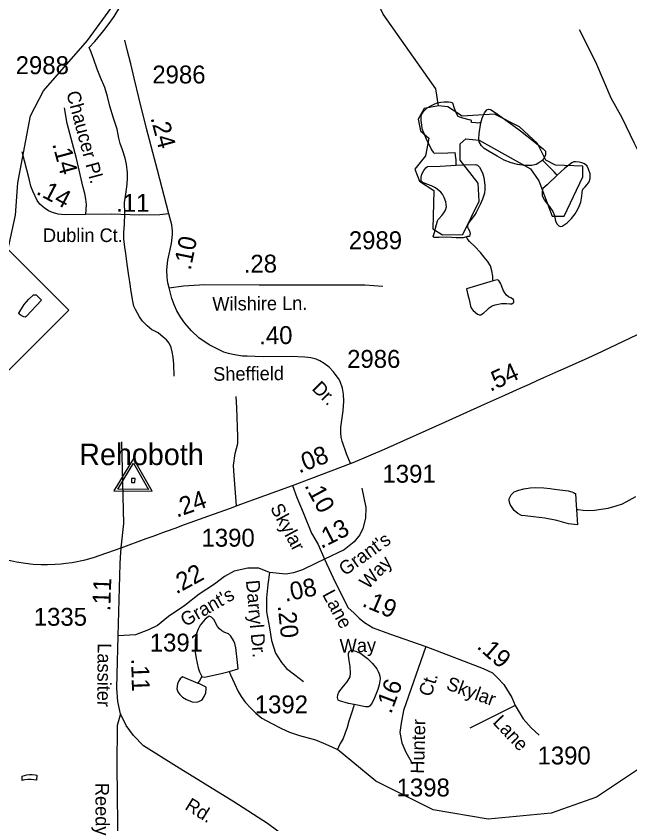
# Model space of a CAD drawing. Extents: x 2082433 to 2279600, y 546599 to 755198.
# Drawn here: x 2142696 to 2146984, y 638629 to 644267 of the extents above; entities that cross this region are included whole.
import ezdxf

# ---------------------------------------------------------------- set-up
doc = ezdxf.new("R2010")
doc.units = 0
for name, color, linetype in [('Exist Hydrographic Creek Single Shore', 7, 'Continuous'), ('Exist Hydrographic Misc Water Feature', 7, 'Continuous'), ('Exist Hydrographic Pond Under 1500 Sq Ft', 7, 'Continuous'), ('Exist Road Non-System Type 51', 7, 'Continuous'), ('Exist Road Primary NC Attributed', 7, 'Continuous'), ('Exist Road Primary NC Service Mileage Hundredths English Label', 7, 'Continuous'), ('Exist Road Primary NC Shield CELL', 7, 'Continuous'), ('Exist Road Secondary Mileage Hundredths English Label', 7, 'Continuous'), ('Exist Road Secondary Type 51 Attributed', 7, 'Continuous'), ('Exist Road Secondary Type 51 Label', 7, 'Continuous'), ('Exist Road Secondary Type 51 Number Label', 7, 'Continuous'), ('Exist Survey Geodetic Marker CELL', 7, 'Continuous'), ('Exist Survey Geodetic Marker Label', 7, 'Continuous')]:
    doc.layers.add(name, color=color, linetype=linetype)

msp = doc.modelspace()

# ---------------------------------------------------------------- linework, layer by layer
at = {"layer": 'Exist Hydrographic Creek Single Shore'}
for points in [[(2144184.1, 639693.2), (2144194.2, 639669.4), (2144220.4, 639607.4), (2144246.7, 639553.6), (2144268.8, 639517.8), (2144297.1, 639477.8), (2144335, 639436), (2144371.3, 639400.5), (2144413.2, 639366.5), (2144477.3, 639330.9), (2144549.7, 639295.2), (2144605.7, 639269.3), (2144675.8, 639245.7), (2144736.1, 639230.1), (2144787.8, 639214.2), (2144844.2, 639192.7), (2144902.4, 639166.8), (2144940.3, 639146.9)], [(2148888.3, 639225.1), (2148289, 639204.5), (2147722.8, 639068.4), (2147448.9, 639051), (2147373.8, 639065.6), (2147098.8, 639048.2), (2146749.8, 638815.8), (2146433.8, 638704.2), (2145992.8, 638660.7), (2145608.9, 638727.5), (2145207.8, 638925.9), (2144940.3, 639146.9)]]:
    msp.add_lwpolyline(points, dxfattribs=at)
at = {"layer": 'Exist Hydrographic Misc Water Feature'}
for points in [[(2142425.9, 640770.2), (2142423.9, 641127.8), (2142389.8, 641502.4), (2142471.8, 641668.1), (2142495.8, 641926.7), (2142528.9, 642021.2), (2142625.9, 642576.9), (2142691.9, 642877.3), (2142706.9, 643103.4), (2142796.9, 643570.6), (2142887.9, 643745.9), (2143194.9, 644097.2), (2143509.1, 644530.4), (2143681.9, 644891), (2143781, 645174.4), (2143996.1, 645534.1), (2144103.9, 645600.8), (2144321.1, 645602.9), (2144613.1, 645452.7), (2144805, 645419.3)], [(2145645.9, 643640.7), (2145628.1, 643759.1), (2145260, 644281.6), (2145134.1, 644546.6), (2144882.1, 644853.5), (2144907.1, 645046.5)], [(2143205.2, 644047.4), (2143245, 644089.7), (2143308.7, 644166), (2143346.5, 644214.2), (2143380.3, 644264.3), (2143419.9, 644330.5), (2143435.7, 644354.4), (2143461.9, 644386.6), (2143491.7, 644422.6), (2143529.4, 644464.8), (2143571.2, 644509.2), (2143585.2, 644527.3), (2143600.7, 644557), (2143620.6, 644599.4), (2143626.8, 644621.2), (2143642, 644697.2)], [(2143800.9, 641753), (2143797, 641836.8), (2143792.7, 641886.9), (2143786.7, 641922.7), (2143778.5, 641952.7), (2143764, 641982.9), (2143746.3, 642006.7), (2143724.2, 642026.6), (2143687.9, 642056.5), (2143660, 642070.4), (2143643.8, 642078.2), (2143611.6, 642106.1), (2143577.8, 642138), (2143557.7, 642167.8), (2143529.4, 642219.6), (2143519.3, 642243.4), (2143510.9, 642277.5), (2143500.7, 642343.5), (2143490.2, 642411.6), (2143484.1, 642453.5), (2143471.8, 642535.3), (2143463.4, 642609.2), (2143455.2, 642655), (2143449.2, 642713.1), (2143448.8, 642757), (2143452.5, 642815.2), (2143456.4, 642889.2), (2143453.7, 642965.1), (2143461.5, 643025.1), (2143471.1, 643093), (2143473, 643137), (2143473, 643173), (2143466.4, 643232.9), (2143458.6, 643275), (2143438.5, 643332.8), (2143421.9, 643376.6), (2143413.9, 643414.8), (2143401.6, 643478.7), (2143375.6, 643554.4), (2143350.8, 643638.5), (2143335, 643706.2), (2143314.7, 643768), (2143286.4, 643838.1), (2143261.8, 643897.7), (2143239.6, 643963.9), (2143219.5, 644015.6), (2143205.2, 644047.4)], [(2145664, 643664.6), (2145630.3, 643656.3), (2145618.2, 643652.4), (2145590.8, 643638.3), (2145566.4, 643624.2), (2145536.4, 643595.8), (2145527, 643581.9), (2145522.5, 643568), (2145522.7, 643537.9), (2145527, 643506), (2145530.7, 643482), (2145540.9, 643454.1), (2145557.3, 643414.3), (2145597.9, 643334.3), (2145609.8, 643316.3), (2145615.6, 643310.6), (2145711.5, 643312.7), (2145763.4, 643315)], [(2145876.6, 643525.4), (2145876.6, 643537.6), (2145872.5, 643541.4), (2145860.6, 643543.6), (2145816.7, 643555.1), (2145794.8, 643561.3), (2145784.8, 643567.2), (2145770.4, 643590.9), (2145758.3, 643621.1), (2145746.4, 643659.1), (2145734.1, 643664.9), (2145716.3, 643666.8), (2145685.9, 643666.5), (2145664, 643664.6)], [(2145942.8, 643521.8), (2145950.8, 643553.9), (2145968.5, 643591.7), (2145984.3, 643612.1), (2145996.4, 643618), (2146010.5, 643614.2), (2146042.5, 643594.4), (2146166.6, 643504.6), (2146218.8, 643467.1), (2146264.8, 643431.4), (2146333.3, 643375.6), (2146377.6, 643339.7), (2146393.6, 643323.9), (2146395.4, 643311.8), (2146393.6, 643298), (2146386, 643278), (2146373.9, 643261.6)], [(2145942.8, 643521.8), (2145932.6, 643521.8), (2145920.9, 643519.9), (2145906.8, 643521.6), (2145876.6, 643525.4)], [(2146373.9, 643261.6), (2146367.7, 643255.6), (2146347.6, 643241.6), (2146330.2, 643231.7), (2146298.2, 643223.5), (2146250, 643223.1), (2146197.9, 643231), (2146154, 643242.9), (2146105.9, 643262.4), (2146055.6, 643290.3), (2145999.6, 643322.2), (2145965.6, 643342), (2145947.6, 643361.7), (2145931, 643389.8), (2145929.3, 643409.9), (2145931, 643447.8), (2145942.8, 643521.8)], [(2145770, 643227.2), (2145770, 643237.3), (2145770.2, 643263.3), (2145765.7, 643295.1), (2145763.4, 643315)], [(2146476.2, 643156.1), (2146406.5, 643090), (2146376.5, 643064), (2146372.8, 643053.7), (2146370.8, 643039.8), (2146370.8, 643013.8), (2146374.7, 643003.9), (2146387.2, 642981.8), (2146405, 642955.9), (2146419.4, 642940), (2146445.4, 642902.4), (2146457.5, 642876.2), (2146465.3, 642836.5), (2146475.8, 642814.2), (2146487.7, 642802.3), (2146497.7, 642798.8), (2146509.6, 642800.6), (2146545.9, 642824.7), (2146575.4, 642854.7), (2146601.3, 642886.9), (2146621.2, 642919.2), (2146631, 642944.9), (2146640.8, 642969), (2146648.4, 643009.1), (2146650.5, 643037.2), (2146656.2, 643059.1), (2146670.6, 643075.2), (2146684.7, 643091.3), (2146700.3, 643111.2), (2146706, 643133.5), (2146705.8, 643165.1), (2146695.8, 643199.1), (2146685.5, 643219.3), (2146665.7, 643235.3), (2146647.8, 643242.8), (2146629.8, 643246.8), (2146603.7, 643248.7), (2146591.4, 643248.9), (2146577.7, 643242.5), (2146526, 643202.5), (2146476.2, 643156.1)], [(2146476.2, 643156.1), (2146468.2, 643164.2), (2146454.2, 643180.1), (2146426.2, 643207.8), (2146391.7, 643243.9), (2146373.9, 643261.6)], [(2145842.2, 642725.6), (2145818.2, 642719.4), (2145770, 642719.4), (2145706, 642723), (2145650.4, 642720.8), (2145628.3, 642720.9), (2145618.7, 642720.8), (2145614.6, 642724.7), (2145610.5, 642730.6), (2145614.1, 642742.6), (2145620.5, 642762.7), (2145626, 642786.6), (2145632.2, 642812.9), (2145640, 642836.8), (2145643.9, 642846.8), (2145649.4, 642852.8), (2145669.7, 642874.9), (2145683.2, 642894.8), (2145695.6, 642912.8), (2145701.5, 642935), (2145701.1, 642950.9), (2145697.2, 642970.9), (2145687.4, 643000.8), (2145675.3, 643022.9), (2145663.2, 643038.9), (2145626.9, 643068.8), (2145599, 643082.3), (2145564.7, 643094.3), (2145536.6, 643106.3), (2145524.9, 643118.2), (2145524.7, 643142.2), (2145530.5, 643164.1), (2145544.2, 643188.3), (2145558.2, 643208.1), (2145570.3, 643216.4), (2145658, 643218.6), (2145770, 643227.2)], [(2145770, 643227.2), (2145826.2, 643229.2), (2145905.9, 643231.8), (2145919.9, 643226), (2145934.2, 643212.1), (2145954.1, 643173.8), (2145964.4, 643140.2), (2145970.5, 643086.1), (2145970.5, 643058.1), (2145967.2, 643030.3), (2145954.9, 642989.9), (2145937.1, 642952), (2145919.3, 642913.8), (2145909.6, 642895.8), (2145899.4, 642877.9), (2145873.9, 642847.7), (2145859.6, 642825.9), (2145850, 642805.9), (2145850, 642793.7), (2145853.9, 642783.8), (2145863.9, 642767.6), (2145868.4, 642747.9), (2145866.2, 642739.8), (2145863.9, 642731.6), (2145860.2, 642727.7), (2145850, 642727.6), (2145842.2, 642725.6)], [(2146027.7, 642418.4), (2146025.5, 642428.5), (2146025.7, 642452.4), (2146018.9, 642488.7), (2146009.3, 642524.7), (2145989, 642556.5), (2145966.8, 642584.2), (2145940.8, 642616.1), (2145900.4, 642657.9), (2145862.3, 642693.7), (2145848.1, 642713.7), (2145842.2, 642725.6)], [(2146027.7, 642418.4), (2145935.7, 642392.2), (2145842.2, 642363.7), (2145852.2, 642321.7), (2145860.2, 642288), (2145870.3, 642241.9), (2145878.3, 642226.1), (2145888.7, 642211.9), (2145918.9, 642186.3), (2145931, 642182), (2145942.8, 642182.3), (2145964.4, 642196.4), (2145984.3, 642214.5), (2146000.7, 642230.7), (2146022, 642244.5), (2146042.3, 642250.8), (2146086, 642260.8), (2146122.1, 642261), (2146146.1, 642259.4), (2146160, 642259.3), (2146168.4, 642265.4), (2146172.3, 642271.3), (2146174.1, 642277.5), (2146170.2, 642289), (2146152.2, 642301), (2146136.2, 642307.1), (2146122.1, 642319), (2146109.8, 642335), (2146099.5, 642354.8), (2146089.5, 642379.1), (2146081.9, 642398.9), (2146075.7, 642410.7), (2146067.5, 642420.9), (2146059.5, 642426.6), (2146047.4, 642424.8), (2146027.7, 642418.4)], [(2142873.2, 642284.7), (2142765.8, 642170.4), (2142758, 642166.3), (2142749.8, 642168.4), (2142729.9, 642176.2), (2142717.4, 642186.2), (2142715.7, 642194.2), (2142721.7, 642204.2), (2142751.2, 642254.1), (2142785.5, 642290.3), (2142816.6, 642322.5), (2142824.6, 642322.5), (2142836.7, 642320.7), (2142873.2, 642284.7)], [(2146610.3, 640823.6), (2146618.7, 640715.7), (2146554.5, 640723.4), (2146472.7, 640745.1), (2146390.7, 640762.7), (2146310.7, 640772.4), (2146252.5, 640778), (2146226.4, 640779.9), (2146200.8, 640793.9), (2146176.4, 640815.9), (2146148.5, 640857.8), (2146140.1, 640883.8), (2146140.3, 640897.6), (2146153.8, 640925.5), (2146175.8, 640945.7), (2146208, 640957.9), (2146243.9, 640966.3), (2146287.7, 640974.2), (2146325.5, 640976.2), (2146381.7, 640974.6), (2146427.6, 640968.9), (2146457.9, 640965.1), (2146553.7, 640953.4), (2146577.9, 640945.3), (2146590, 640941.5), (2146597.8, 640937.4), (2146603.9, 640933.7), (2146608, 640853.6), (2146610.3, 640823.6)], [(2146610.3, 640823.6), (2146622.4, 640821.8), (2146656.6, 640817.9), (2146696.6, 640815.9), (2146736.6, 640818.3), (2146782.1, 640824.4), (2146832, 640832.7), (2146888.3, 640848.9), (2146932.2, 640863), (2146977.9, 640887.3), (2147025.7, 640913.7)], [(2144184.1, 639693.2), (2144246, 639709.8), (2144241.7, 639755.5), (2144231.5, 639857.6), (2144222.9, 639887.7), (2144215.1, 639909.6), (2144196.6, 639939.5), (2144179, 639955.1), (2144152.9, 639965.2), (2144132.9, 639975.1), (2144116.9, 639990.9), (2144102.5, 640006.9), (2144076.5, 640055), (2144060.5, 640070.8), (2144044.3, 640078.5), (2144038.1, 640074.6), (2144016.8, 640058.4), (2143980.5, 640014.4), (2143966.8, 639988.5), (2143955.1, 639958.2), (2143946.9, 639912.4), (2143945.6, 639876.1), (2143945.6, 639848.1), (2143945.8, 639826.2), (2143953.8, 639782.4), (2143968.2, 639718.6), (2143978, 639688.7), (2143994.4, 639656.6)], [(2145056.8, 639461.4), (2145016.8, 639469.1), (2144954.9, 639487), (2144946.9, 639492.7), (2144940.6, 639510.6), (2144942.6, 639528.6), (2144950.4, 639546.9), (2144982.4, 639589.1), (2145008.2, 639619.2), (2145030, 639654.9), (2145031.8, 639681), (2145029.7, 639727.1), (2145023.6, 639769.1), (2145017.2, 639802.8), (2145017, 639817), (2145019.3, 639824.8), (2145025.2, 639832.8), (2145033.4, 639840.9), (2145041, 639841), (2145069.1, 639833.1), (2145105.2, 639817.5), (2145151.3, 639783.8), (2145185.4, 639747.8), (2145215.5, 639710), (2145225.8, 639691.8), (2145231.9, 639675.9), (2145237.9, 639660), (2145240.1, 639640.2), (2145232.1, 639600), (2145222.7, 639566.2), (2145212.7, 639542.1), (2145200.6, 639507.8), (2145180.7, 639467.8), (2145165.1, 639449.9), (2145157.1, 639445.8), (2145137, 639445.6), (2145056.8, 639461.4)], [(2143994.4, 639656.6), (2143998.3, 639654.4), (2144012.5, 639652.6), (2144128.1, 639678.9), (2144184.1, 639693.2)], [(2143966.6, 639608.5), (2143858.5, 639654), (2143842.3, 639641.9), (2143832.4, 639628), (2143822.8, 639605.9), (2143818.7, 639571.6), (2143824.9, 639550), (2143839, 639532.1), (2143858.9, 639512), (2143885.4, 639496.3), (2143925.1, 639480.1), (2143955.1, 639478.5), (2143973.1, 639482.6), (2143995.1, 639494.7), (2144010.6, 639516.6), (2144020.9, 639542.7), (2144024.6, 639572.5), (2144024.6, 639582.7), (2143976.8, 639606.6), (2143966.6, 639608.5)], [(2143966.6, 639608.5), (2143968.4, 639612.7), (2143978.4, 639626.6), (2143994.4, 639656.6)], [(2145056.8, 639461.4), (2145044.9, 639423.1), (2145021.3, 639345.2), (2145007.6, 639301), (2144993.5, 639257.3), (2144979.9, 639224.9), (2144960.4, 639188.9), (2144948.3, 639164.8), (2144940.3, 639146.9)], [(2142737.9, 638961.3), (2142771.7, 638971.6), (2142789.6, 638973.4), (2142807.4, 638973.5), (2142829.7, 638969.7), (2142839.6, 638967.8), (2142837.7, 638933.6), (2142799.8, 638937.7), (2142778.1, 638937.4), (2142757.8, 638935.6), (2142745.9, 638933.3), (2142737.9, 638931.3), (2142737.9, 638961.3)]]:
    msp.add_lwpolyline(points, dxfattribs=at)
at = {"layer": 'Exist Hydrographic Pond Under 1500 Sq Ft'}
msp.add_lwpolyline([(2145645.9, 643640.7), (2145546, 643623), (2145504, 643548.4), (2145521, 643466.1), (2145580.1, 643415.7), (2145555.9, 643291.5), (2145481, 643197.9), (2145515.1, 643115.2), (2145614.9, 643050.8), (2145608, 642782), (2145675, 642741.3), (2145815.9, 642741.7), (2145931.9, 642975.5), (2145922.9, 643100.3), (2145797, 643260.4), (2145797, 643375.2), (2145838, 643410.4), (2145929.9, 643402), (2146288.9, 643201.1), (2146348, 643117.9), (2146440.9, 642870.1), (2146523.9, 642871.6), (2146656, 643144.5), (2146656, 643220), (2146464.1, 643227.1), (2146397, 643261.3), (2146338, 643377.3), (2146213.1, 643494.6), (2146036.9, 643583.5), (2145813, 643568.4), (2145711.9, 643632.8), (2145645.9, 643640.7)], dxfattribs=at)
at = {"layer": 'Exist Road Non-System Type 51'}
msp.add_line((2146182.7, 639455.6), (2145865.1, 639295.9), dxfattribs=at)
for points in [[(2147115.2, 643177.8), (2147016.1, 643378.7), (2146930.1, 643557.7), (2146853.8, 643693.7), (2146746.8, 643944.6), (2146631.8, 644171.8)], [(2144236.5, 640848.8), (2144219.4, 641059.2), (2144214.1, 641129.4), (2144226.4, 641213.6), (2144244, 641283.8), (2144245.7, 641332.9), (2144237, 641532.9), (2144233.4, 641611.9)], [(2143428.6, 640556.3), (2143447.4, 640724.1), (2143434.3, 641295.2)]]:
    msp.add_lwpolyline(points, dxfattribs=at)
at = {"layer": 'Exist Road Primary NC Attributed'}
for points in [[(2145032.1, 641143.3), (2145051, 641150.5), (2145270.1, 641244.2), (2145695, 641434.1), (2145967.9, 641557.5), (2146113.7, 641622.8), (2146217.4, 641669.7), (2146281.6, 641698.9), (2146337.1, 641723.4), (2146383.8, 641743.6), (2146487.8, 641790.2), (2146502.7, 641796.9), (2146667.1, 641870.3), (2146752.5, 641909.1), (2147032.3, 642042.7), (2147097.6, 642075.5), (2147190.4, 642121.3), (2147256, 642153.8), (2147379.5, 642214.9), (2147576, 642311.5), (2147625.7, 642335.8)], [(2144627.3, 640990.4), (2145032.1, 641143.3)], [(2143428.6, 640556.3), (2143604.1, 640619.5), (2143653, 640637.4), (2143690.7, 640651.2), (2143713.8, 640659.8), (2143746.6, 640671.4), (2143806.3, 640693.3), (2143872, 640717.3), (2143911, 640731.7), (2144075.7, 640790.4), (2144199.4, 640835), (2144239.7, 640850), (2144627.3, 640990.4)], [(2142635.2, 640470.6), (2142698.7, 640456.8), (2142762.4, 640447.5), (2142815, 640442.3), (2142871, 640439.3), (2142915, 640438.6), (2142968.6, 640440.4), (2143011.5, 640443.8), (2143044, 640447.9), (2143087.5, 640453.8), (2143177.5, 640472.1), (2143235.3, 640488.9), (2143428.6, 640556.3)]]:
    msp.add_lwpolyline(points, dxfattribs=at)
at = {"layer": 'Exist Road Primary NC Shield CELL'}
msp.add_lwpolyline([(2141065.9, 642214.1), (2142064.9, 643213.1), (2143063.9, 642214.1), (2142064.9, 641215.1)], close=True, dxfattribs=at)
at = {"layer": 'Exist Road Secondary Type 51 Attributed'}
for points in [[(2143763.6, 642885.7), (2143683.8, 643191.5), (2143607.5, 643482.9), (2143552.5, 643699.2), (2143523, 643825.1), (2143497.6, 643933.4), (2143471.6, 644030.9), (2143456, 644098.5)], [(2143183.7, 642882.8), (2143187.1, 642951.4), (2143183.6, 642988.3), (2143174.9, 643027.6), (2143164.9, 643071.1), (2143118.7, 643273.3), (2143053, 643518), (2143034.5, 643625.9)], [(2143183.7, 642882.8), (2143042.9, 642879.6), (2143012.8, 642882.3), (2142988.7, 642885.5), (2142950.6, 642895.7), (2142922.4, 642907.5), (2142891.8, 642927.9), (2142861.2, 642955.2), (2142843.1, 642980.8), (2142811.4, 643045.8), (2142799.6, 643080.1), (2142786.2, 643131.1), (2142738, 643320.4)], [(2143763.6, 642885.7), (2143698.8, 642879.9), (2143561, 642878.6), (2143360, 642884), (2143183.7, 642882.8)], [(2143764.8, 642370.3), (2143756.7, 642406), (2143751.5, 642441.9), (2143749.8, 642495.8), (2143755, 642562.6), (2143780.6, 642679.1), (2143788.6, 642741.6), (2143789.4, 642768.3), (2143784.2, 642810.4), (2143763.6, 642885.7)], [(2143764.8, 642370.3), (2143864.5, 642384.6), (2144013.2, 642393.6), (2144394.8, 642390.9), (2144835.5, 642391.9), (2145131.7, 642390.9), (2145258.1, 642382.2)], [(2145032.1, 641143.3), (2145004.4, 641210.5), (2144973.5, 641300.3), (2144967.5, 641328.3), (2144964.2, 641359.2), (2144963.6, 641398.4), (2144980.5, 641510.9), (2144985.4, 641579.7), (2144983.8, 641628.6), (2144976, 641670.4), (2144960.4, 641717), (2144947.6, 641737.3), (2144932.5, 641758.1), (2144913.7, 641784.5), (2144881.9, 641815.7), (2144848.4, 641841.8), (2144818.3, 641860.9), (2144791.3, 641873), (2144754.2, 641881.6), (2144713.7, 641886.9), (2144618.2, 641890.9), (2144422.2, 641888.6), (2144309.8, 641892.1), (2144277.8, 641893.8), (2144249.4, 641899), (2144210.6, 641904.8), (2144180.5, 641912.9), (2144146.9, 641921), (2144127.2, 641929.7), (2144045.4, 641972.3), (2143972.6, 642022.3), (2143920.2, 642069.1), (2143875.2, 642124), (2143846.9, 642162.6), (2143818.6, 642208.9), (2143802.4, 642246.9), (2143784.8, 642296), (2143764.8, 642370.3)], [(2144627.3, 640990.4), (2144657.8, 640907.2), (2144701.9, 640800.8), (2144759.5, 640657.6), (2144805.9, 640577.5), (2144849.4, 640476.4)], [(2145112.1, 640970.8), (2145140.2, 640836), (2145136, 640762.9), (2145119.1, 640689.9), (2145096.6, 640646.3), (2145058.7, 640597.2), (2144988.5, 640541), (2144849.4, 640476.4)], [(2143408.9, 639941.2), (2143422.6, 640443.7), (2143425.2, 640488.1), (2143428.6, 640556.3)], [(2144849.4, 640476.4), (2144787.6, 640445.5), (2144697.5, 640402.2), (2144632.6, 640381.1), (2144579.7, 640372.4), (2144465.9, 640383.6)], [(2144849.4, 640476.4), (2144925.9, 640315.3), (2145014.5, 640137.2), (2145054.6, 640101.3), (2145093.2, 640064.4), (2145130, 640034.6), (2145191.4, 639996), (2145305.4, 639955.6), (2145559, 639867)], [(2144465.9, 640383.6), (2144392.2, 640412.7), (2144315, 640412.7), (2144220.3, 640393.4), (2144151.8, 640354.8), (2144082.2, 640302.5), (2143973.8, 640231.1), (2143873.7, 640153.9), (2143761.5, 640075), (2143682.5, 640013.6), (2143621.1, 639982), (2143529.7, 639948.2), (2143408.9, 639941.2)], [(2144465.9, 640383.6), (2144454.7, 640299.4), (2144444.9, 640206.7), (2144444.9, 640109.7), (2144465.2, 639996), (2144479.3, 639907.5), (2144507.4, 639820.4), (2144549.5, 639755.8), (2144584.6, 639713.6), (2144642.9, 639668.7), (2144704.7, 639622.3)], [(2143425.1, 639397.6), (2143406.8, 639483.2), (2143399.8, 639576), (2143401.9, 639670.1), (2143408.9, 639941.2)], [(2145559, 639867), (2145401.4, 639420.1), (2145385.3, 639331.9), (2145376.5, 639267), (2145390.5, 639195.1), (2145418.6, 639130.1), (2145466, 639047.7)], [(2145559, 639867), (2145857.2, 639753), (2145958.1, 639713.5), (2146023, 639681.9), (2146058.1, 639646.8), (2146103.8, 639601.2), (2146158.1, 639510), (2146182.7, 639455.6), (2146238.8, 639362.6), (2146295, 639299.4), (2146351.1, 639248.6)], [(2143425.1, 639397.6), (2143402.6, 639316.1), (2143399.8, 639030.9), (2143407.5, 638425.5)], [(2144605.7, 638518.2), (2144452.6, 638632), (2144218, 638782.3), (2143815.6, 639028.1), (2143585.2, 639174.2), (2143515, 639244.5), (2143464.4, 639316.1), (2143425.1, 639397.6)]]:
    msp.add_lwpolyline(points, dxfattribs=at)
at = {"layer": 'Exist Survey Geodetic Marker CELL'}
for points in [[(2143647, 640950.2), (2143515.7, 641177.8), (2143379.6, 640953.4)], [(2143621.2, 640962.6), (2143405.7, 640965.2), (2143515.4, 641146)], [(2143526.1, 641010.3), (2143526.4, 641038.6), (2143502.1, 641038.9), (2143501.8, 641010.6)]]:
    msp.add_lwpolyline(points, close=True, dxfattribs=at)

# ---------------------------------------------------------------- texts
at = {"layer": 'Exist Road Primary NC Service Mileage Hundredths English Label'}
for s, rotation, p in [('.54', 24.3712, (2146008.2, 641643.6)), ('.08', 20.6886, (2144672.4, 641074.2)), ('.24', 19.604, (2143818.6, 640765.2))]:
    msp.add_text(s, height=125, rotation=rotation, dxfattribs=at).set_placement(p)
at = {"layer": 'Exist Road Secondary Mileage Hundredths English Label'}
for s, rotation, p in [('.24', 284.9075, (2143633.7, 643556.5)), ('.14', 285.0464, (2142947.4, 643374.5)), ('.14', 332.411, (2142829.7, 643027.9)), ('.11', 0, (2143394.5, 642900.9)), ('.10', 78.4533, (2143914.9, 642488.2)), ('.28', 0.5143, (2144286.6, 642475.2)), ('.40', 0.6031, (2144394.9, 641975.8)), ('.10', 298.5055, (2144707.7, 640990.2)), ('.13', 27.0276, (2144827.9, 640547.3)), ('.22', 28.4267, (2143814.6, 640229.4)), ('.11', 87.9468, (2143352.9, 640111.6)), ('.08', 11.8419, (2144577, 640178.2)), ('.19', 337.0969, (2145106.9, 640150.6)), ('.20', 275.9469, (2144523.1, 640151)), ('.19', 318.7971, (2145908.6, 639859.1)), ('.11', 271.485, (2143499.5, 639781.7)), ('.16', 69.4553, (2145315.3, 639391.4))]:
    msp.add_text(s, height=125, rotation=rotation, dxfattribs=at).set_placement(p)
at = {"layer": 'Exist Road Secondary Type 51 Label'}
for s, rotation, p in [('Chaucer Pl.', 285.0464, (2143045.4, 643731)), ('Wilshire Ln.', 0.5143, (2144067.3, 642210.6)), ('Sheffield', 0.6031, (2144073, 641721.2)), ('Dr.', 315, (2144757.3, 641661.6)), ('Skylar', 298.2764, (2144468, 640833.9)), ("Grant's", 35.6852, (2144993.4, 640356.1)), ('Way', 46.5363, (2145154.1, 640261.7)), ('Darryl Dr.', 275.1711, (2144301.3, 640326.7)), ("Grant's", 29.5836, (2143877.7, 640002)), (' Lane', 298.2764, (2144815.3, 640261.2)), ('Way', 1.2402, (2144957.4, 639823.8)), ('Lassiter', 269.5071, (2143265.9, 639889.6)), ('Ct.', 72.4255, (2145595.5, 639510.8)), ('Skylar', 339.9271, (2145693.9, 639570)), ('Hunter', 88.5128, (2145545.9, 638977.6)), (' Lane', 313.5402, (2145996, 639359.1)), ('Reedy', 270.1709, (2143249.7, 638914.6)), ('Rd.', 328.2683, (2143868.4, 638734.7))]:
    msp.add_text(s, height=95, rotation=rotation, dxfattribs=at).set_placement(p)
msp.add_text('Dublin Ct.', height=95, dxfattribs=at).set_placement((2142883.3, 642690))
at = {"layer": 'Exist Road Secondary Type 51 Number Label'}
for s, p in [('2988', (2142692.7, 643861.9)), ('2986', (2143647.4, 643796.9)), ('2989', (2145020.2, 642640)), ('2986', (2145008.4, 641811.7)), ('1391', (2145255.3, 641010.1)), ('1390', (2143991.1, 640563.6)), ('1335', (2142819.1, 640011.3)), ('1391', (2143629.5, 639831.6)), ('1392', (2144363.2, 639400)), ('1390', (2146338.7, 639043.2)), ('1398', (2145354.1, 638820))]:
    msp.add_text(s, height=125, dxfattribs=at).set_placement(p)
at = {"layer": 'Exist Survey Geodetic Marker Label'}
msp.add_text('Rehoboth', height=150, dxfattribs=at).set_placement((2143136.6, 641132.8))

doc.saveas('drawing.dxf')
